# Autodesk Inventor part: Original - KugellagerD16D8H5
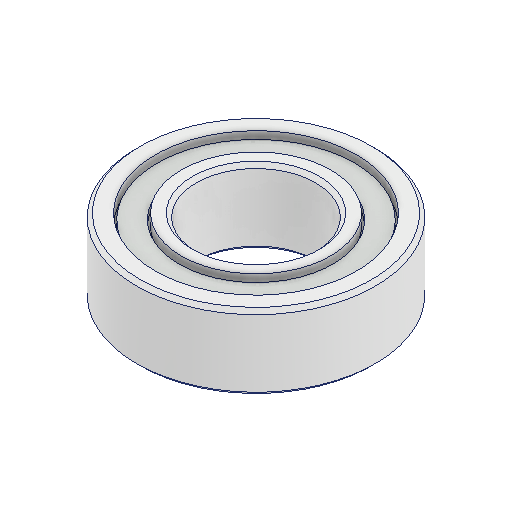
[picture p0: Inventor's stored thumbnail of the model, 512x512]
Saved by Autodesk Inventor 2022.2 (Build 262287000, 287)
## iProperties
Created: 2024-09
Part Number: Original - KugellagerD16D8H5
Material: Generico
Document SubType Name: Modeling
Designer: 18907419
Density: 1 g/cm^3
Appearance: Default
Author: 18907419
Revision Number: ANY
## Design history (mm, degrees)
feature "Schnitt-Linear austragen5"
node "Solido1"
